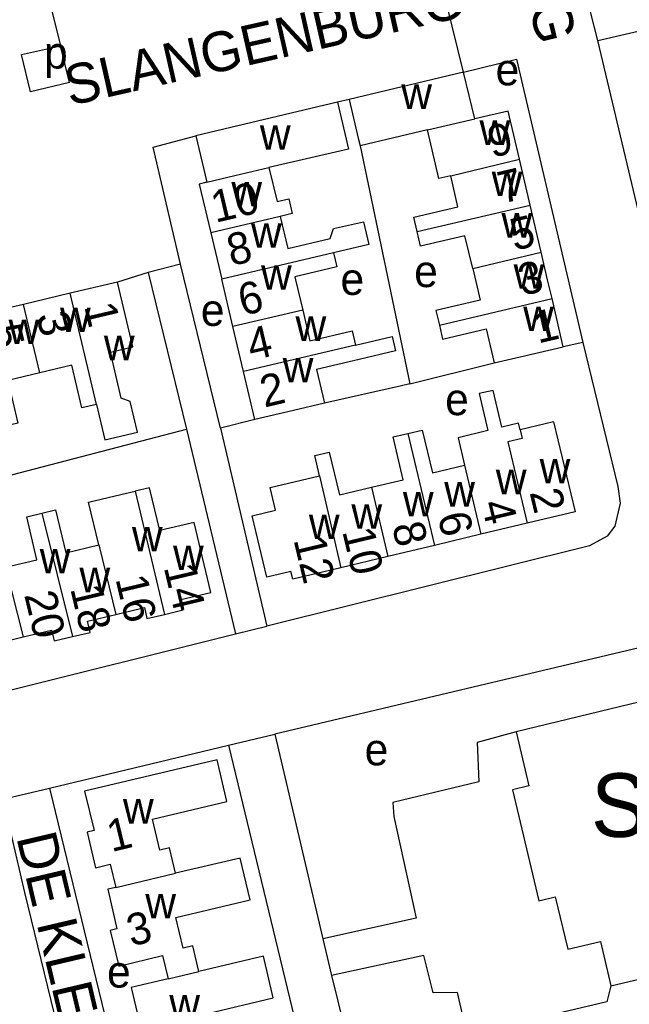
# Model space of a CAD drawing. Extents: x 157646 to 159241, y 379213 to 381217.
# Drawn here: x 158541.6 to 158618.3, y 380658.9 to 380782.7 of the extents above; entities that cross this region are included whole.
import ezdxf

# ---------------------------------------------------------------- set-up
doc = ezdxf.new("R2010")
doc.units = 0
for name, color, linetype in [('BLT_Basislijn', 7, 'Continuous'), ('BLT_Bebouwing', 7, 'Continuous'), ('BLT_Bebouwing_beschrifting', 7, 'Continuous'), ('BLT_Centroide', 7, 'Continuous'), ('BLT_Huisnummer', 7, 'Continuous'), ('BLT_Huisnummer_ tussenligend', 7, 'Continuous'), ('BLT_Onderverdeling_panden', 7, 'Continuous'), ('BLT_Straatnaam', 7, 'Continuous')]:
    doc.layers.add(name, color=color, linetype=linetype)

msp = doc.modelspace()

# ---------------------------------------------------------------- linework, layer by layer
at = {"layer": 'BLT_Basislijn'}
for p, q in [((158543.41, 380792.93), (158546.69, 380779.45)), ((158614.29, 380780.12), (158612.52, 380787.11)), ((158597.41, 380776.13), (158595.26, 380784.81)), ((158541.81, 380778.35), (158546.69, 380779.45)), ((158547.82, 380774.81), (158546.69, 380779.45)), ((158542.94, 380773.64), (158541.81, 380778.35)), ((158547.82, 380774.81), (158542.94, 380773.64)), ((158583.01, 380772.7), (158581.56, 380772.35)), ((158584.41, 380766.84), (158590.65, 380736.92)), ((158561.82, 380751.97), (158557.74, 380750.93)), ((158566.84, 380731.34), (158561.82, 380751.97)), ((158557.74, 380750.93), (158553.86, 380749.71)), ((158557.74, 380750.93), (158562.57, 380731.2)), ((158612.43, 380742.09), (158609.96, 380741.57)), ((158590.65, 380736.92), (158601.28, 380739.54)), ((158571.15, 380732.41), (158566.84, 380731.34)), ((158519.62, 380720.04), (158562.57, 380731.2)), ((158562.57, 380731.2), (158568.7, 380705.44)), ((158566.84, 380731.34), (158572.68, 380706.44)), ((158651.04, 380711.19), (158573.67, 380692.82)), ((158568.7, 380705.44), (158572.68, 380706.44)), ((158478.68, 380683.08), (158568.7, 380705.44)), ((158567.85, 380691.44), (158573.67, 380692.82)), ((158573.67, 380692.82), (158579.7, 380667.11)), ((158545.31, 380686.05), (158567.85, 380691.44)), ((158567.85, 380691.44), (158580.51, 380638.99)), ((158539.43, 380684.65), (158545.31, 380686.05)), ((158545.31, 380686.05), (158558.07, 380633.72)), ((158579.7, 380667.11), (158580.8, 380662.49)), ((158580.8, 380662.49), (158586.2, 380640.34))]:
    msp.add_line(p, q, dxfattribs=at)
for points in [[(158614.29, 380780.12), (158659.93, 380790.72), (158666.37, 380763.79)], [(158620.7, 380753.14), (158620.62, 380753.47), (158614.29, 380780.12)], [(158597.41, 380776.13), (158604.09, 380777.77), (158612.43, 380742.09)], [(158561.82, 380751.97), (158558.38, 380766.69), (158563.74, 380768.1)], [(158612.43, 380742.09), (158616.83, 380723.99), (158617.12, 380721.89), (158616.45, 380719.01), (158615.5, 380717.74), (158613.24, 380716.51), (158572.68, 380706.44)], [(158590.65, 380736.92), (158589.61, 380736.67), (158579.91, 380734.48)], [(158604.02, 380693.15), (158599.11, 380691.79), (158599.34, 380686.85), (158588.51, 380684.23), (158588.65, 380682.47), (158591.44, 380669.7), (158579.7, 380667.11)], [(158539.43, 380684.65), (158542.18, 380672.91), (158552.08, 380632.31)], [(158615.94, 380661.19), (158615.45, 380659.17), (158598.09, 380655.07), (158597.77, 380655.38), (158596.64, 380660.35), (158593.6, 380660.3), (158592.43, 380664.98), (158580.8, 380662.49)]]:
    msp.add_lwpolyline(points, dxfattribs=at)
at = {"layer": 'BLT_Bebouwing'}
for p, q in [((158597.41, 380776.13), (158583.01, 380772.7)), ((158598.81, 380770.25), (158597.41, 380776.13)), ((158581.56, 380772.35), (158567.26, 380768.94)), ((158567.26, 380768.94), (158563.74, 380768.1)), ((158592.89, 380768.86), (158584.41, 380766.84)), ((158563.74, 380768.1), (158565.13, 380762.27)), ((158605.79, 380759.38), (158604.43, 380765.18)), ((158607.17, 380753.49), (158605.79, 380759.38)), ((158565.61, 380755.91), (158566.99, 380750.07)), ((158553.86, 380749.71), (158547.92, 380748.3)), ((158568.4, 380744.11), (158566.99, 380750.07)), ((158547.92, 380748.3), (158542.05, 380746.91)), ((158542.05, 380746.91), (158536.27, 380745.55)), ((158609.96, 380741.57), (158608.54, 380747.63)), ((158569.73, 380738.46), (158568.4, 380744.11)), ((158571.15, 380732.41), (158569.73, 380738.46)), ((158608.74, 380732.12), (158604.53, 380731.11)), ((158605.43, 380719.37), (158599.6, 380717.98)), ((158599.6, 380717.98), (158593.75, 380716.58)), ((158593.75, 380716.58), (158587.9, 380715.18)), ((158587.9, 380715.18), (158581.99, 380713.77)), ((158615.94, 380661.19), (158626.58, 380663.71))]:
    msp.add_line(p, q, dxfattribs=at)
for points in [[(158583.01, 380772.7), (158584.17, 380767.83), (158584.41, 380766.84)], [(158581.56, 380772.35), (158582.95, 380766.45), (158572.93, 380764.12)], [(158604.43, 380765.18), (158603.02, 380771.23), (158598.81, 380770.25)], [(158595.79, 380763.08), (158594.32, 380762.73), (158593.9, 380764.54), (158592.89, 380768.86)], [(158572.93, 380764.12), (158573.95, 380759.83), (158575.42, 380760.18), (158575.86, 380758.33), (158574.34, 380757.98)], [(158591.59, 380756.06), (158591.16, 380757.88), (158596.7, 380759.18), (158595.79, 380763.08)], [(158565.13, 380762.27), (158564.16, 380762.04), (158565.61, 380755.91)], [(158574.34, 380757.98), (158575.3, 380753.93), (158580.63, 380755.19), (158581.05, 380756.44), (158584.82, 380757.3), (158585.48, 380754.43), (158581.06, 380753.4)], [(158598.56, 380751.4), (158597.59, 380755.54), (158592.01, 380754.24), (158591.59, 380756.06)], [(158581.06, 380753.4), (158581.48, 380751.61), (158576.19, 380750.36), (158576.28, 380750), (158577.17, 380746.17)], [(158608.54, 380747.63), (158607.98, 380750), (158607.17, 380753.49)], [(158598.56, 380751.4), (158599.49, 380747.45), (158593.94, 380746.14), (158594.37, 380744.31)], [(158551.23, 380734.33), (158552.28, 380729.86), (158556.39, 380730.84), (158555.47, 380734.7), (158554.35, 380735.11), (158552.98, 380740.89), (158555.79, 380741.56), (158553.86, 380749.71)], [(158577.17, 380746.17), (158578.07, 380742.33), (158583.4, 380743.59), (158583.83, 380741.79)], [(158594.37, 380744.31), (158594.78, 380742.55), (158600.27, 380743.84), (158601.28, 380739.54)], [(158583.83, 380741.79), (158588.43, 380742.85), (158588.85, 380741.07), (158584.26, 380739.99), (158578.9, 380738.72), (158579.91, 380734.48)], [(158601.28, 380739.54), (158605.09, 380740.43), (158609.96, 380741.57)], [(158551.23, 380734.33), (158549.4, 380733.89), (158548.13, 380739.24), (158544.09, 380738.29)], [(158544.09, 380738.29), (158540.06, 380737.33), (158541.32, 380731.98), (158539.58, 380731.56)], [(158604.53, 380731.11), (158604.33, 380731.95), (158602.22, 380731.44), (158601.13, 380736.09), (158599.36, 380735.68), (158600.45, 380731.02), (158596.72, 380730.13), (158597.52, 380726.67)], [(158579.91, 380734.48), (158576.02, 380733.56), (158571.15, 380732.41)], [(158608.74, 380732.12), (158611.44, 380720.81), (158605.43, 380719.37)], [(158585.81, 380723.89), (158589.83, 380724.85), (158588.55, 380730.23), (158590.38, 380730.67)], [(158590.38, 380730.67), (158592.21, 380731.1), (158593.51, 380725.71), (158597.52, 380726.67)], [(158579.28, 380725.35), (158578.68, 380727.88), (158580.51, 380728.31), (158581.8, 380722.93), (158585.81, 380723.89)], [(158581.99, 380713.77), (158575.92, 380712.32), (158575.69, 380713.31), (158572.68, 380712.59), (158570.83, 380720.3), (158573.77, 380721.01), (158573.08, 380723.87), (158579.28, 380725.35)], [(158551.51, 380716.66), (158550.24, 380722.01), (158554.31, 380722.98), (158556.11, 380723.41)], [(158559.8, 380707.9), (158562.15, 380708.46), (158561.84, 380709.79), (158565.6, 380710.68), (158563.5, 380719.47), (158559.19, 380718.45), (158557.91, 380723.83), (158556.11, 380723.41)], [(158539.8, 380713.85), (158543.73, 380714.78), (158542.45, 380720.18), (158544.37, 380720.64)], [(158544.37, 380720.64), (158546.09, 380721.05), (158547.37, 380715.67), (158551.51, 380716.66)], [(158553.67, 380707.91), (158557.25, 380708.76), (158557.58, 380707.38), (158559.8, 380707.9)], [(158548.21, 380705.11), (158550.45, 380705.64), (158550.11, 380707.06), (158553.67, 380707.91)], [(158541.99, 380705.07), (158545.59, 380705.92), (158545.92, 380704.56), (158548.21, 380705.11)], [(158536.52, 380702.34), (158538.72, 380702.86), (158538.4, 380704.21), (158541.99, 380705.07)], [(158661.92, 380665.14), (158658.96, 380677.58), (158652.07, 380675.95), (158650.52, 380682.46), (158653.3, 380683.11), (158650.05, 380696.82), (158647.76, 380696.28), (158646.13, 380703.18), (158631.33, 380699.68), (158618.43, 380696.62), (158604.02, 380693.15)], [(158604.02, 380693.15), (158605.64, 380686.32), (158603.58, 380685.83), (158606.89, 380671.88), (158608.95, 380672.37), (158610.51, 380665.79), (158614.62, 380666.76), (158615.94, 380661.19)], [(158566.4, 380689.6), (158549.74, 380685.66), (158550.92, 380680.7), (158550.05, 380680.5), (158551.1, 380676.04), (158552.97, 380676.47), (158553.68, 380673.57)], [(158561.19, 380675.34), (158560.43, 380678.54), (158559.21, 380678.26), (158558.29, 380682.15), (158567.64, 380684.36), (158566.4, 380689.6)], [(158564.1, 380662.97), (158563.34, 380666.19), (158562.12, 380665.9), (158561.2, 380669.79), (158570.56, 380672.01), (158569.32, 380677.26), (158561.19, 380675.34)], [(158553.68, 380673.57), (158552.67, 380673.33), (158553.8, 380668.35), (158552.97, 380668.15), (158554.03, 380663.67), (158559.55, 380664.98), (158560.23, 380662.07)], [(158567.04, 380650.62), (158566.27, 380653.85), (158565.05, 380653.56), (158564.13, 380657.44), (158573.47, 380659.65), (158572.23, 380664.9), (158564.1, 380662.97)], [(158560.23, 380662.07), (158555.58, 380660.97), (158556.75, 380656.01), (158555.89, 380655.81), (158556.95, 380651.32), (158559.31, 380651.87), (158560, 380648.96)]]:
    msp.add_lwpolyline(points, dxfattribs=at)
at = {"layer": 'BLT_Onderverdeling_panden'}
for p, q in [((158592.89, 380768.86), (158598.81, 380770.25)), ((158595.79, 380763.08), (158604.43, 380765.18)), ((158591.59, 380756.06), (158605.79, 380759.38)), ((158574.34, 380757.98), (158565.61, 380755.91)), ((158581.06, 380753.4), (158566.99, 380750.07)), ((158598.56, 380751.4), (158607.17, 380753.49)), ((158551.23, 380734.33), (158547.92, 380748.3)), ((158544.09, 380738.29), (158542.05, 380746.91)), ((158594.37, 380744.31), (158608.54, 380747.63)), ((158577.17, 380746.17), (158568.4, 380744.11)), ((158583.83, 380741.79), (158569.73, 380738.46)), ((158590.38, 380730.67), (158593.75, 380716.58)), ((158597.52, 380726.67), (158599.6, 380717.98)), ((158579.28, 380725.35), (158581.99, 380713.77)), ((158556.11, 380723.41), (158559.8, 380707.9)), ((158585.81, 380723.89), (158587.9, 380715.18)), ((158544.37, 380720.64), (158548.21, 380705.11)), ((158551.51, 380716.66), (158553.67, 380707.91)), ((158539.8, 380713.85), (158541.99, 380705.07)), ((158553.68, 380673.57), (158561.19, 380675.34)), ((158560.23, 380662.07), (158564.1, 380662.97))]:
    msp.add_line(p, q, dxfattribs=at)
for points in [[(158565.13, 380762.27), (158568.65, 380763.1), (158572.93, 380764.12)], [(158604.53, 380731.11), (158604.79, 380730.05), (158602.97, 380729.62), (158605.43, 380719.37)]]:
    msp.add_lwpolyline(points, dxfattribs=at)

# ---------------------------------------------------------------- texts
at = {"layer": 'BLT_Bebouwing_beschrifting'}
msp.add_text('School', height=8, dxfattribs=at).set_placement((158613.44, 380679.91))
at = {"layer": 'BLT_Centroide'}
for s, p in [('p', (158544.63, 380776.57)), ('e', (158601.44, 380774.46)), ('w', (158589.57, 380771.5)), ('w', (158599.42, 380766.97)), ('w', (158571.79, 380766.35)), ('w', (158600.95, 380760.53)), ('w', (158568.2, 380759.24)), ('w', (158602.19, 380755.31)), ('w', (158570.67, 380754.03)), ('w', (158571.93, 380748.75)), ('e', (158591.2, 380749.08)), ('w', (158603.7, 380748.88)), ('e', (158581.93, 380748.1)), ('w', (158546.64, 380743.44)), ('e', (158564.36, 380744.2)), ('w', (158604.91, 380743.56)), ('w', (158576.27, 380742.31)), ('w', (158540.17, 380741.91)), ('w', (158552.16, 380739.88)), ('w', (158574.66, 380737.09)), ('e', (158595.1, 380732.97)), ('w', (158606.98, 380724.39)), ('w', (158601.47, 380723.03)), ('w', (158594.98, 380721.47)), ('w', (158589.78, 380720.23)), ('w', (158583.3, 380718.67)), ('w', (158577.95, 380717.38)), ('w', (158555.69, 380715.84)), ('w', (158544.09, 380713.06)), ('w', (158560.86, 380713.5)), ('w', (158549.09, 380710.7)), ('e', (158584.97, 380688.92)), ('w', (158554.56, 380681.59)), ('w', (158557.37, 380669.66)), ('e', (158552.56, 380660.96)), ('w', (158560.39, 380656.94))]:
    msp.add_text(s, height=4, dxfattribs=at).set_placement(p)
at = {"layer": 'BLT_Huisnummer'}
for s, rotation, p in [('9', 13.1484, (158600.98, 380765.33)), ('10', 13.3177, (158566.19, 380757.15)), ('5', 13.1686, (158603.79, 380753.64)), ('6', 13.1728, (158569.6, 380745.45)), ('1', 283.3223, (158549.66, 380746.68)), ('1', 13.1578, (158606.78, 380741.97)), ('5', 283.3156, (158537.68, 380743.91)), ('2', 13.3193, (158572.34, 380733.91)), ('2', 283.4465, (158605.7, 380723.27)), ('6', 283.4462, (158594.12, 380720.32)), ('12', 283.4474, (158576, 380717.31)), ('14', 283.3934, (158559.68, 380713.83)), ('18', 283.3934, (158547.91, 380711.17)), ('1', 13.692, (158553.11, 380677.99)), ('3', 13.692, (158555.59, 380666.11))]:
    msp.add_text(s, height=4, rotation=rotation, dxfattribs=at).set_placement(p)
at = {"layer": 'BLT_Huisnummer_ tussenligend'}
for s, rotation, p in [('7', 13.1686, (158602.26, 380759.57)), ('8', 13.1728, (158568.18, 380751.71)), ('3', 13.1578, (158604.82, 380747.96)), ('3', 283.3223, (158543.65, 380745.51)), ('4', 13.3193, (158570.72, 380739.81)), ('4', 283.4465, (158599.62, 380721.85)), ('8', 283.4462, (158588.39, 380719.06)), ('10', 283.4462, (158582.13, 380718.37)), ('16', 283.3934, (158553.6, 380712.39)), ('20', 283.3934, (158542.12, 380710.38))]:
    msp.add_text(s, height=4, rotation=rotation, dxfattribs=at).set_placement(p)
at = {"layer": 'BLT_Straatnaam'}
for s, height, rotation, p in [('WIJENBURG', 5, 283.6232, (158597.4, 380818.35)), ('SLANGENBURG', 4.9999, 12.7469, (158547.86, 380771.87)), ('DE KLENCKE', 5, 283.2468, (158541.13, 380679.88))]:
    msp.add_text(s, height=height, rotation=rotation, dxfattribs=at).set_placement(p)

doc.saveas('drawing.dxf')
